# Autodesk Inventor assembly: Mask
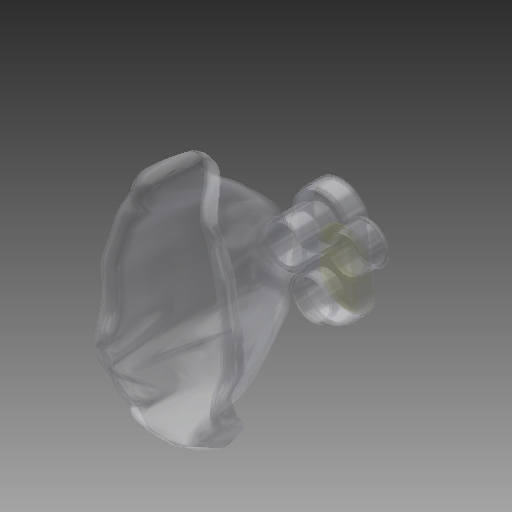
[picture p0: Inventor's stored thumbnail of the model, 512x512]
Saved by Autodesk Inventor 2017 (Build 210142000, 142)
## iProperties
Created: 2020-03
Part Number: Mask
Description: SolidWorks IGES file using analytic representation for surfaces
Document SubType Name: Assembly
Designer: user
Sending System: SolidWorks 2014
Preprocessor: SolidWorks 2014
Minimum Resolution: 0.0
Sending System Product ID: assembly.SLDASM
Receiving System Product ID: assembly.SLDASM
Sent Units: Millimeter
Translation Standard: IGES 5.3
Model Creation Time: 2020-03-21
Author: usuario
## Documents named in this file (5)
- C:\Users\user\Documents\Inventor\Home Ventilator CPAP\Mask.iam
- C:\Users\user\Documents\Inventor\MASK\medical mask.ipt
- C:\Users\user\Documents\Inventor\MASK\BODY VALVE.ipt
- C:\Users\user\Documents\Inventor\MASK\flap.ipt
- C:\Users\user\Documents\Inventor\MASK\BODY VALVE 1.ipt
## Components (4 placed, 4 different names)
1. medical mask
2. BODY VALVE
3. flap
4. BODY VALVE 1
